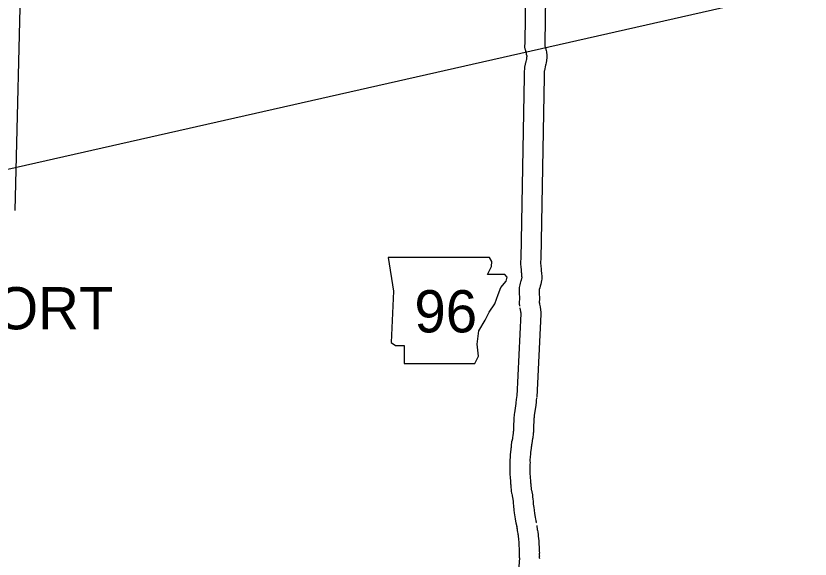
# Model space of a CAD drawing. Extents: x 1370567 to 1373900, y 377514 to 379648.
# Drawn here: x 1371037.6 to 1371156.9, y 379246.9 to 379328.5 of the extents above; entities that cross this region are included whole.
import ezdxf

# ---------------------------------------------------------------- set-up
doc = ezdxf.new("R2010")
doc.units = 0
doc.layers.add('Default', color=7, linetype='Continuous')
doc.layers.add('Survey Names', color=7, linetype='Continuous')

msp = doc.modelspace()

# ---------------------------------------------------------------- linework, layer by layer
at = {"layer": 'Default'}
for points in [[(1371114.6, 379360.98), (1371114.08, 379324.52), (1371114.07, 379324.39), (1371114.06, 379324.23), (1371114.06, 379324.19), (1371114.05, 379324.05), (1371114.05, 379323.79), (1371114.1, 379323.54), (1371114.12, 379323.4), (1371114.17, 379323.26), (1371114.17, 379323.24), (1371114.21, 379323.05), (1371114.26, 379322.93), (1371114.27, 379322.88), (1371114.3, 379322.7), (1371114.37, 379322.49), (1371114.38, 379322.45), (1371114.37, 379322.37), (1371114.35, 379322.21), (1371114.35, 379322.18), (1371114.32, 379321.95), (1371114.31, 379321.9), (1371114.29, 379321.84), (1371114.22, 379321.63), (1371114.18, 379321.38), (1371114.14, 379321.25), (1371114.12, 379321.14), (1371114.09, 379321.01), (1371114.05, 379320.77), (1371114.05, 379320.69), (1371114.03, 379320.6), (1371114.02, 379320.42), (1371114, 379320.21), (1371114, 379320.1), (1371113.97, 379319.9), (1371113.97, 379319.68), (1371113.98, 379319.62), (1371113.97, 379319.55), (1371113.97, 379319.37), (1371113.46, 379292.05), (1371113.45, 379291.55), (1371113.45, 379291.37), (1371113.44, 379291.17), (1371113.47, 379290.86), (1371113.48, 379290.69), (1371113.51, 379290.44), (1371113.52, 379290.33), (1371113.53, 379290.23), (1371113.55, 379290), (1371113.56, 379289.86), (1371113.57, 379289.75), (1371113.6, 379289.36), (1371113.61, 379289.32), (1371113.56, 379288.94), (1371113.55, 379288.87), (1371113.52, 379288.77), (1371113.49, 379288.68), (1371113.47, 379288.63), (1371113.43, 379288.54), (1371113.36, 379288.33), (1371113.31, 379288.11), (1371113.24, 379287.72), (1371113.24, 379287.55), (1371113.24, 379287.34), (1371113.24, 379287.27), (1371113.24, 379287.15), (1371113.26, 379285.85), (1371113.25, 379285.63), (1371113.25, 379285.54), (1371113.25, 379285.49), (1371113.25, 379285.44), (1371113.25, 379285.39), (1371113.25, 379285.22), (1371113.28, 379285.03), (1371113.29, 379284.93), (1371113.3, 379284.91), (1371113.3, 379284.88)], [(1371117.58, 379359.23), (1371117.08, 379324.37), (1371117.06, 379324.24), (1371117.06, 379324.2), (1371117.06, 379324.05), (1371117.1, 379323.9), (1371117.11, 379323.88), (1371117.21, 379323.51), (1371117.23, 379323.43), (1371117.28, 379323.28), (1371117.32, 379323.08), (1371117.35, 379322.91), (1371117.38, 379322.68), (1371117.38, 379322.27), (1371117.37, 379322.23), (1371117.36, 379322.01), (1371117.34, 379321.93), (1371117.34, 379321.79), (1371117.27, 379321.41), (1371117.23, 379321.22), (1371117.19, 379321.08), (1371117.17, 379320.98), (1371117.14, 379320.89), (1371117.11, 379320.76), (1371117.06, 379320.57), (1371117.06, 379320.53), (1371117.02, 379320.25), (1371117, 379320.15), (1371117, 379320.13), (1371117, 379320.07), (1371117, 379320.06), (1371116.99, 379319.86), (1371116.98, 379319.75), (1371116.99, 379319.6), (1371116.97, 379319.41), (1371116.97, 379319.33), (1371116.46, 379291.98), (1371116.45, 379291.49), (1371116.45, 379291.34), (1371116.44, 379291.26), (1371116.46, 379291.07), (1371116.46, 379290.99), (1371116.49, 379290.81), (1371116.51, 379290.6), (1371116.52, 379290.44), (1371116.54, 379290.21), (1371116.55, 379290.09), (1371116.56, 379290), (1371116.58, 379289.7), (1371116.61, 379289.51), (1371116.63, 379289.23), (1371116.61, 379288.97), (1371116.59, 379288.77), (1371116.54, 379288.49), (1371116.52, 379288.45), (1371116.47, 379288.22), (1371116.39, 379287.88), (1371116.31, 379287.65), (1371116.26, 379287.52), (1371116.25, 379287.49), (1371116.24, 379287.46), (1371116.24, 379287.45), (1371116.24, 379287.44), (1371116.25, 379287.27), (1371116.24, 379287.06), (1371116.26, 379285.86), (1371116.25, 379285.6), (1371116.25, 379285.51), (1371116.25, 379285.46), (1371116.25, 379285.42), (1371116.26, 379285.36), (1371116.28, 379285.23)], [(1371037.53, 379299.24), (1371038.47, 379337.82), (1371038.34, 379337.88), (1371036.94, 379338.56)], [(1371116.22, 379285.52), (1371116.27, 379285.35), (1371116.29, 379285.18), (1371116.36, 379284.81), (1371116.38, 379284.69), (1371116.45, 379284.43), (1371116.45, 379284.26), (1371116.46, 379284.13), (1371116.48, 379283.93), (1371116.48, 379283.69), (1371115.86, 379271.26)], [(1371113.34, 379284.65), (1371113.4, 379284.32), (1371113.42, 379284.21), (1371113.45, 379284.02), (1371113.46, 379283.96), (1371113.47, 379283.94), (1371113.47, 379283.88), (1371113.48, 379283.83), (1371113.48, 379283.78), (1371112.87, 379271.41)], [(1371112.88, 379271.54), (1371112.82, 379271.14), (1371112.8, 379270.94), (1371112.78, 379270.8), (1371112.78, 379270.72), (1371112.74, 379270.54), (1371112.73, 379270.31), (1371112.52, 379268.89), (1371112.5, 379268.69), (1371112.48, 379268.56), (1371112.47, 379268.46), (1371112.43, 379268.25), (1371112.45, 379268.04), (1371112.45, 379268.03), (1371112.45, 379267.93), (1371112.38, 379266.89), (1371112.38, 379266.7), (1371112.38, 379266.5), (1371112.36, 379266.36), (1371112.36, 379266.15), (1371112.35, 379266.13), (1371112.33, 379265.9), (1371112.32, 379265.79), (1371112.29, 379265.55), (1371112.28, 379265.46), (1371112.28, 379265.44), (1371112.23, 379265.25), (1371112.21, 379265), (1371112.21, 379265), (1371112.18, 379264.82), (1371112.17, 379264.79), (1371112.1, 379264.54), (1371112.09, 379264.36), (1371112.05, 379264.12), (1371112.04, 379263.96), (1371112.02, 379263.8), (1371112.02, 379263.68), (1371112.02, 379263.68), (1371112, 379263.55), (1371111.97, 379263.33), (1371111.95, 379263.09), (1371111.93, 379262.93), (1371111.9, 379262.67), (1371111.88, 379262.42), (1371111.86, 379262.15), (1371111.84, 379261.89), (1371111.84, 379261.59), (1371111.85, 379261.4), (1371111.84, 379261.3), (1371111.84, 379261.11), (1371111.82, 379260.57), (1371111.82, 379260.46), (1371111.82, 379260.3), (1371111.83, 379260.12), (1371111.83, 379260.06), (1371111.83, 379259.89), (1371111.83, 379259.54), (1371111.86, 379259.31), (1371111.87, 379259.17), (1371111.88, 379259.05), (1371111.91, 379258.78), (1371111.91, 379258.65), (1371111.93, 379258.41), (1371111.94, 379258.23), (1371111.96, 379258.06), (1371111.97, 379257.93), (1371112, 379257.72), (1371112.05, 379257.31), (1371112.05, 379257.13), (1371112.1, 379256.82), (1371112.12, 379256.72), (1371112.16, 379256.52), (1371112.18, 379256.44), (1371112.22, 379256.17), (1371112.23, 379256.16), (1371112.31, 379255.61), (1371112.34, 379255.34), (1371112.36, 379254.91), (1371112.43, 379254.28), (1371112.49, 379253.88), (1371112.57, 379253.27), (1371112.63, 379253), (1371112.68, 379252.65), (1371112.74, 379252.36), (1371112.81, 379252.03), (1371112.85, 379251.86), (1371112.89, 379251.67), (1371112.95, 379251.48)], [(1371115.85, 379271.13), (1371115.8, 379270.75), (1371115.78, 379270.59), (1371115.77, 379270.53), (1371115.76, 379270.31), (1371115.73, 379270.17), (1371115.72, 379270), (1371115.5, 379268.52), (1371115.48, 379268.3), (1371115.46, 379268.17), (1371115.45, 379268.02), (1371115.45, 379267.9), (1371115.44, 379267.72), (1371115.38, 379266.79), (1371115.38, 379266.67), (1371115.38, 379266.43), (1371115.37, 379266.35), (1371115.37, 379266.19), (1371115.36, 379266.12), (1371115.36, 379265.98), (1371115.34, 379265.81), (1371115.32, 379265.61), (1371115.31, 379265.51), (1371115.29, 379265.31), (1371115.28, 379265.23), (1371115.27, 379265.13), (1371115.24, 379264.97), (1371115.22, 379264.86), (1371115.2, 379264.78), (1371115.2, 379264.75), (1371115.19, 379264.59), (1371115.15, 379264.32), (1371115.12, 379264.21), (1371115.09, 379264.08), (1371115.08, 379264.04), (1371115.07, 379263.88), (1371115.03, 379263.72), (1371115.02, 379263.71), (1371115.02, 379263.65), (1371115.02, 379263.62), (1371115.01, 379263.52), (1371114.99, 379263.3), (1371114.97, 379263.15), (1371114.95, 379263.01), (1371114.93, 379262.77), (1371114.91, 379262.59), (1371114.89, 379262.39), (1371114.87, 379262.14), (1371114.85, 379261.93), (1371114.84, 379261.79), (1371114.84, 379261.69), (1371114.86, 379261.4), (1371114.84, 379261.18), (1371114.84, 379261.03), (1371114.82, 379260.49), (1371114.82, 379260.44), (1371114.84, 379260.27), (1371114.83, 379260.04), (1371114.83, 379259.87), (1371114.83, 379259.71), (1371114.84, 379259.65), (1371114.86, 379259.43), (1371114.87, 379259.31), (1371114.9, 379259.01), (1371114.91, 379258.85), (1371114.93, 379258.61), (1371114.93, 379258.5), (1371114.95, 379258.35), (1371114.96, 379258.27), (1371114.98, 379258.09), (1371115.05, 379257.45), (1371115.05, 379257.38), (1371115.05, 379257.37), (1371115.07, 379257.28), (1371115.07, 379257.27), (1371115.14, 379257.04), (1371115.21, 379256.6), (1371115.25, 379256.34), (1371115.25, 379256.23), (1371115.28, 379255.99), (1371115.33, 379255.59), (1371115.35, 379255.17), (1371115.41, 379254.67), (1371115.46, 379254.3), (1371115.53, 379253.78), (1371115.59, 379253.52), (1371115.63, 379253.18), (1371115.68, 379252.96), (1371115.74, 379252.67), (1371115.77, 379252.53), (1371115.79, 379252.44), (1371115.81, 379252.4)], [(1371112.88, 379251.88), (1371112.89, 379251.57), (1371112.93, 379251.3), (1371112.95, 379251.19), (1371112.96, 379251.05), (1371113.02, 379250.68), (1371113.06, 379250.51), (1371113.09, 379250.26), (1371113.11, 379250.02), (1371113.13, 379249.76), (1371113.16, 379249.58), (1371113.18, 379249.44), (1371113.19, 379249.3), (1371113.2, 379249.1), (1371113.2, 379248.9), (1371113.23, 379248.52), (1371113.24, 379248.46), (1371113.25, 379248.28), (1371113.25, 379248.18), (1371113.25, 379247.98), (1371113.25, 379247.98), (1371113.25, 379247.62), (1371113.25, 379247.46), (1371113.25, 379247.33), (1371113.25, 379247.28), (1371113.25, 379247.15), (1371113.26, 379246.96)], [(1371115.88, 379251.99), (1371115.88, 379251.86), (1371115.89, 379251.78), (1371115.93, 379251.54), (1371115.94, 379251.4), (1371115.97, 379251.22), (1371116.02, 379251), (1371116.08, 379250.56), (1371116.1, 379250.27), (1371116.11, 379250.16), (1371116.13, 379250.01), (1371116.17, 379249.69), (1371116.18, 379249.48), (1371116.2, 379249.2), (1371116.2, 379249), (1371116.21, 379248.92), (1371116.23, 379248.78), (1371116.24, 379248.42), (1371116.25, 379248.27), (1371116.25, 379248.06), (1371116.27, 379247.87), (1371116.25, 379247.7), (1371116.25, 379247.6), (1371116.25, 379247.54), (1371116.26, 379247.41), (1371116.25, 379247.26), (1371116.25, 379247.17), (1371116.26, 379247.04)], [(1371113.26, 379247.1), (1371113.09, 379244.48)]]:
    msp.add_lwpolyline(points, dxfattribs=at)
msp.add_lwpolyline([(1371093.57, 379292.21), (1371094.33, 379287.13), (1371093.99, 379279.43), (1371094.67, 379279.01), (1371095.94, 379279.01), (1371095.94, 379276.31), (1371106.59, 379276.31), (1371107.1, 379277.4), (1371106.93, 379279.18), (1371107.19, 379281.21), (1371108.12, 379282.82), (1371108.71, 379284), (1371109.55, 379285.27), (1371110.06, 379286.63), (1371110.48, 379287.72), (1371111.25, 379288.66), (1371111.41, 379289.25), (1371111.08, 379289.67), (1371108.45, 379289.67), (1371109.05, 379290.85), (1371109.13, 379291.62), (1371108.78, 379292.2)], close=True, dxfattribs=at)
at = {"layer": 'Survey Names'}
msp.add_line((1371498.51, 379409.91), (1370792.1, 379250.17), dxfattribs=at)

# ---------------------------------------------------------------- texts
at = {"layer": 'Default'}
for s, p in [('FORT', (1371029.22, 379281.42)), ('96', (1371097.49, 379280.96))]:
    msp.add_text(s, height=6.336, dxfattribs=at).set_placement(p)

doc.saveas('drawing.dxf')
